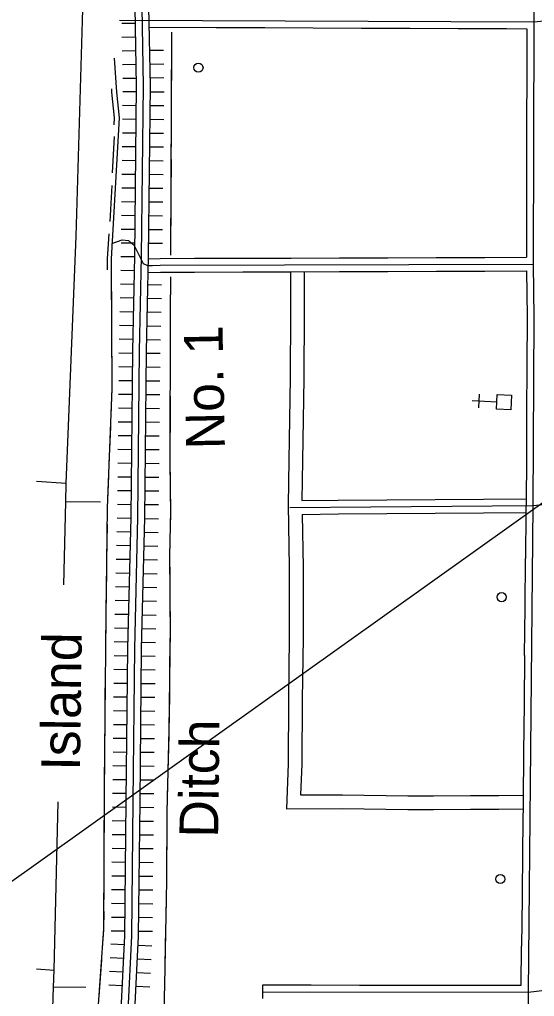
# Model space of a CAD drawing. Extents: x -4306 to 3843, y 131 to 8053.
# Drawn here: x -2826 to -1926, y 1950 to 3654 of the extents above; entities that cross this region are included whole.
import ezdxf

# ---------------------------------------------------------------- set-up
doc = ezdxf.new("R2010")
doc.units = 0
for name, color, linetype in [('29', 7, 'Continuous'), ('31', 7, 'Continuous'), ('32', 7, 'Continuous'), ('4', 7, 'Continuous'), ('43', 7, 'Continuous'), ('45', 7, 'Continuous'), ('46', 7, 'Continuous'), ('5', 7, 'Continuous'), ('56', 7, 'Continuous'), ('57', 7, 'Continuous'), ('R_No Plot', 7, 'Continuous')]:
    doc.layers.add(name, color=color, linetype=linetype)

msp = doc.modelspace()

# ---------------------------------------------------------------- linework, layer by layer
at = {"layer": '29'}
for p, q in [((-2609.1, 3538.2), (-2611.5, 3675.3)), ((-2623, 3647), (-2647, 3646.6)), ((-2622.6, 3623), (-2646.6, 3622.6)), ((-2622.2, 3599.1), (-2646.2, 3598.6)), ((-2622.2, 3599.1), (-2646.2, 3598.6)), ((-2574.2, 3599.9), (-2598.2, 3599.5)), ((-2574.2, 3599.9), (-2598.2, 3599.5)), ((-2621.8, 3575.1), (-2645.8, 3574.6)), ((-2573.8, 3575.9), (-2597.8, 3575.5)), ((-2621.3, 3551.1), (-2645.3, 3550.6)), ((-2573.3, 3551.9), (-2597.3, 3551.5)), ((-2621.2, 3527.4), (-2645.2, 3527.6)), ((-2621.2, 3527.4), (-2645.2, 3527.6)), ((-2612.3, 3240.6), (-2609.1, 3538.2)), ((-2573.2, 3526.9), (-2597.2, 3527.1)), ((-2573.2, 3526.9), (-2597.2, 3527.1)), ((-2621.5, 3503.4), (-2645.5, 3503.6)), ((-2573.5, 3502.9), (-2597.5, 3503.1)), ((-2621.8, 3479.4), (-2645.8, 3479.6)), ((-2573.8, 3478.9), (-2597.8, 3479.1)), ((-2622, 3455.4), (-2646, 3455.6)), ((-2622, 3455.4), (-2646, 3455.6)), ((-2574, 3454.9), (-2598, 3455.1)), ((-2574, 3454.9), (-2598, 3455.1)), ((-2622.3, 3431.4), (-2646.3, 3431.6)), ((-2574.3, 3430.9), (-2598.3, 3431.1)), ((-2622.5, 3407.4), (-2646.5, 3407.6)), ((-2574.5, 3406.9), (-2598.5, 3407.1)), ((-2622.8, 3383.4), (-2646.8, 3383.6)), ((-2622.8, 3383.4), (-2646.8, 3383.6)), ((-2574.8, 3382.9), (-2598.8, 3383.1)), ((-2574.8, 3382.9), (-2598.8, 3383.1)), ((-2623.1, 3359.4), (-2647.1, 3359.6)), ((-2575.1, 3358.9), (-2599.1, 3359.1)), ((-2623.3, 3335.4), (-2647.3, 3335.6)), ((-2575.3, 3334.9), (-2599.3, 3335.1)), ((-2623.6, 3311.4), (-2647.6, 3311.6)), ((-2623.6, 3311.4), (-2647.6, 3311.6)), ((-2575.6, 3310.9), (-2599.6, 3311.1)), ((-2575.6, 3310.9), (-2599.6, 3311.1)), ((-2623.8, 3287.4), (-2647.8, 3287.6)), ((-2575.8, 3286.9), (-2599.8, 3287.1)), ((-2624.1, 3263.4), (-2648.1, 3263.6)), ((-2576.1, 3262.9), (-2600.1, 3263.1)), ((-2624.4, 3239.5), (-2648.4, 3240)), ((-2624.4, 3239.5), (-2648.4, 3240)), ((-2615.9, 3075.5), (-2612.3, 3240.6)), ((-2624.9, 3215.5), (-2648.9, 3216)), ((-2625.4, 3191.5), (-2649.4, 3192)), ((-2577.4, 3190.5), (-2601.4, 3191)), ((-2625.9, 3167.5), (-2649.9, 3168)), ((-2625.9, 3167.5), (-2649.9, 3168)), ((-2577.9, 3166.5), (-2601.9, 3167)), ((-2577.9, 3166.5), (-2601.9, 3167)), ((-2626.4, 3143.5), (-2650.4, 3144)), ((-2578.4, 3142.5), (-2602.4, 3143)), ((-2627, 3119.5), (-2651, 3120)), ((-2579, 3118.5), (-2603, 3119)), ((-2627.5, 3095.5), (-2651.5, 3096)), ((-2627.5, 3095.5), (-2651.5, 3096)), ((-2579.5, 3094.5), (-2603.5, 3095)), ((-2579.5, 3094.5), (-2603.5, 3095)), ((-2627.9, 3071.4), (-2651.9, 3071.6)), ((-2618.8, 2784.8), (-2615.9, 3075.5)), ((-2579.9, 3070.9), (-2603.9, 3071.1)), ((-2628.2, 3047.4), (-2652.2, 3047.6)), ((-2580.2, 3046.9), (-2604.2, 3047.1)), ((-2628.4, 3023.4), (-2652.4, 3023.6)), ((-2628.4, 3023.4), (-2652.4, 3023.6)), ((-2580.4, 3022.9), (-2604.4, 3023.1)), ((-2580.4, 3022.9), (-2604.4, 3023.1)), ((-2628.7, 2999.4), (-2652.7, 2999.6)), ((-2580.7, 2998.9), (-2604.7, 2999.1)), ((-2628.9, 2975.4), (-2652.9, 2975.6)), ((-2580.9, 2974.9), (-2604.9, 2975.1)), ((-2629.1, 2951.4), (-2653.1, 2951.6)), ((-2629.1, 2951.4), (-2653.1, 2951.6)), ((-2581.1, 2950.9), (-2605.1, 2951.1)), ((-2581.1, 2950.9), (-2605.1, 2951.1)), ((-2629.4, 2927.4), (-2653.4, 2927.6)), ((-2581.4, 2926.9), (-2605.4, 2927.1)), ((-2629.6, 2903.4), (-2653.6, 2903.6)), ((-2581.6, 2902.9), (-2605.6, 2903.1)), ((-2629.9, 2879.4), (-2653.9, 2879.6)), ((-2629.9, 2879.4), (-2653.9, 2879.6)), ((-2581.8, 2878.9), (-2605.9, 2879.1)), ((-2581.8, 2878.9), (-2605.9, 2879.1)), ((-2630.1, 2855.4), (-2654.1, 2855.6)), ((-2582.1, 2854.9), (-2606.1, 2855.1)), ((-2630.3, 2831.4), (-2654.3, 2831.6)), ((-2582.3, 2830.9), (-2606.3, 2831.1)), ((-2630.6, 2807.4), (-2654.6, 2807.6)), ((-2630.6, 2807.4), (-2654.6, 2807.6)), ((-2582.6, 2806.9), (-2606.6, 2807.1)), ((-2582.6, 2806.9), (-2606.6, 2807.1)), ((-2630.8, 2783.5), (-2654.8, 2784.1)), ((-2624.3, 2556.4), (-2618.8, 2784.8)), ((-2582.8, 2782.4), (-2606.8, 2783)), ((-2631.4, 2759.5), (-2655.4, 2760.1)), ((-2583.4, 2758.4), (-2607.4, 2759)), ((-2632, 2735.5), (-2656, 2736.1)), ((-2632, 2735.5), (-2656, 2736.1)), ((-2584, 2734.4), (-2608, 2735)), ((-2584, 2734.4), (-2608, 2735)), ((-2632.6, 2711.6), (-2656.6, 2712.1)), ((-2584.6, 2710.4), (-2608.6, 2711)), ((-2633.1, 2687.6), (-2657.1, 2688.1)), ((-2585.2, 2686.4), (-2609.1, 2687)), ((-2633.7, 2663.6), (-2657.7, 2664.1)), ((-2633.7, 2663.6), (-2657.7, 2664.1)), ((-2585.7, 2662.4), (-2609.7, 2663)), ((-2585.7, 2662.4), (-2609.7, 2663)), ((-2634.3, 2639.6), (-2658.3, 2640.1)), ((-2586.3, 2638.4), (-2610.3, 2639)), ((-2634.9, 2615.6), (-2658.9, 2616.1)), ((-2586.9, 2614.4), (-2610.9, 2615)), ((-2635.5, 2591.6), (-2659.5, 2592.2)), ((-2635.5, 2591.6), (-2659.5, 2592.2)), ((-2587.5, 2590.4), (-2611.5, 2591)), ((-2587.5, 2590.4), (-2611.5, 2591)), ((-2636, 2567.6), (-2660, 2568.2)), ((-2627.1, 2290.5), (-2624.3, 2556.4)), ((-2588, 2566.4), (-2612, 2567)), ((-2636.4, 2543.4), (-2660.4, 2543.7)), ((-2588.4, 2542.9), (-2612.4, 2543.2)), ((-2636.7, 2519.4), (-2660.7, 2519.7)), ((-2636.7, 2519.4), (-2660.7, 2519.7)), ((-2588.7, 2518.9), (-2612.7, 2519.2)), ((-2588.7, 2518.9), (-2612.7, 2519.2)), ((-2636.9, 2495.4), (-2661, 2495.7)), ((-2588.9, 2494.9), (-2612.9, 2495.2)), ((-2637.2, 2471.4), (-2661.2, 2471.7)), ((-2589.2, 2470.9), (-2613.2, 2471.2)), ((-2637.5, 2447.4), (-2661.5, 2447.7)), ((-2637.5, 2447.4), (-2661.5, 2447.7)), ((-2589.5, 2446.9), (-2613.5, 2447.2)), ((-2589.5, 2446.9), (-2613.5, 2447.2)), ((-2637.7, 2423.4), (-2661.7, 2423.7)), ((-2589.7, 2422.9), (-2613.7, 2423.2)), ((-2638, 2399.4), (-2662, 2399.7)), ((-2590, 2398.9), (-2614, 2399.2)), ((-2638.2, 2375.4), (-2662.2, 2375.7)), ((-2638.2, 2375.4), (-2662.2, 2375.7)), ((-2590.2, 2374.9), (-2614.2, 2375.2)), ((-2590.2, 2374.9), (-2614.2, 2375.2)), ((-2638.5, 2351.4), (-2662.5, 2351.7)), ((-2590.5, 2350.9), (-2614.5, 2351.2)), ((-2638.7, 2327.4), (-2662.7, 2327.7)), ((-2590.7, 2326.9), (-2614.7, 2327.2)), ((-2639, 2303.4), (-2663, 2303.7)), ((-2639, 2303.4), (-2663, 2303.7)), ((-2591, 2302.9), (-2615, 2303.2)), ((-2591, 2302.9), (-2615, 2303.2)), ((-2629.6, 2055.2), (-2627.1, 2290.5)), ((-2639.2, 2279.4), (-2663.2, 2279.7)), ((-2591.2, 2278.9), (-2615.2, 2279.2)), ((-2639.5, 2255.4), (-2663.5, 2255.7)), ((-2591.5, 2254.9), (-2615.5, 2255.1)), ((-2639.7, 2231.4), (-2663.7, 2231.6)), ((-2639.7, 2231.4), (-2663.7, 2231.6)), ((-2591.7, 2230.9), (-2615.7, 2231.1)), ((-2591.7, 2230.9), (-2615.7, 2231.1)), ((-2640, 2207.4), (-2664, 2207.6)), ((-2592, 2206.9), (-2616, 2207.1)), ((-2640.2, 2183.4), (-2664.2, 2183.6)), ((-2592.2, 2182.9), (-2616.2, 2183.1)), ((-2640.5, 2159.4), (-2664.5, 2159.6)), ((-2640.5, 2159.4), (-2664.5, 2159.6)), ((-2592.5, 2158.9), (-2616.5, 2159.1)), ((-2592.5, 2158.9), (-2616.5, 2159.1)), ((-2640.7, 2135.4), (-2664.7, 2135.6)), ((-2592.7, 2134.9), (-2616.7, 2135.1)), ((-2641, 2111.4), (-2665, 2111.6)), ((-2593, 2110.9), (-2617, 2111.1)), ((-2641.2, 2087.4), (-2665.2, 2087.6)), ((-2641.2, 2087.4), (-2665.2, 2087.6)), ((-2593.2, 2086.9), (-2617.2, 2087.1)), ((-2593.2, 2086.9), (-2617.2, 2087.1)), ((-2641.5, 2063.4), (-2665.5, 2063.6)), ((-2593.5, 2062.9), (-2617.5, 2063.1)), ((-2635.9, 1925.3), (-2629.6, 2055.2)), ((-2642.3, 2039.9), (-2666.3, 2041)), ((-2594.4, 2037.5), (-2618.4, 2038.7)), ((-2643.5, 2015.9), (-2667.5, 2017.1)), ((-2643.5, 2015.9), (-2667.5, 2017.1)), ((-2595.6, 2013.5), (-2619.5, 2014.7)), ((-2595.6, 2013.5), (-2619.5, 2014.7)), ((-2644.7, 1991.9), (-2668.7, 1993.1)), ((-2596.7, 1989.6), (-2620.7, 1990.7)), ((-2645.9, 1967.9), (-2669.8, 1969.1)), ((-2597.9, 1965.6), (-2621.9, 1966.8))]:
    msp.add_line(p, q, dxfattribs=at)
at = {"layer": '31'}
for p, q in [((-1939.9, 3558), (-1940, 3473.5)), ((-1940, 3473.5), (-1940.1, 3389)), ((-1940.1, 3389), (-1940.3, 3239.1)), ((-1940.2, 3215.1), (-1939.2, 3135.4)), ((-1939.2, 3133.3), (-1939.6, 3051.1)), ((-1939.2, 3135.4), (-1939.2, 3133.3)), ((-1940.5, 2882.2), (-1940.9, 2817.8)), ((-1940.9, 2817.8), (-1941.1, 2793.8)), ((-1941.1, 2793.8), (-1941.9, 2713.3)), ((-1943.6, 2544.3), (-1944.4, 2459.8)), ((-1944.4, 2459.8), (-1945.3, 2375.3)), ((-1947, 2206.3), (-1947.9, 2121.9)), ((-1947.9, 2121.9), (-1948.7, 2037.4))]:
    msp.add_line(p, q, dxfattribs=at)
for points in [[(-1939.8, 3637.7), (-1939.9, 3558)], [(-1939.6, 3051.1), (-1940.1, 2966.7)], [(-1940.1, 2966.7), (-1940.5, 2882.2)], [(-1942.7, 2628.8), (-1941.9, 2713.3)], [(-1943.6, 2544.3), (-1942.7, 2628.8)], [(-1945.3, 2375.3), (-1946.2, 2290.8)], [(-1946.2, 2290.8), (-1947, 2206.3)], [(-1949.4, 1969.3), (-1948.7, 2037.4)]]:
    msp.add_lwpolyline(points, dxfattribs=at)
at = {"layer": '32'}
for p, q in [((-2650.8, 3652.7), (-1927.7, 3649.7)), ((-1927.7, 3649.7), (-1898.5, 3652.6)), ((-2598.9, 3640.4), (-2481.9, 3640)), ((-2481.9, 3640), (-2397.4, 3639.6)), ((-2397.4, 3639.6), (-2312.9, 3639.3)), ((-2312.9, 3639.3), (-2228.4, 3638.9)), ((-2228.4, 3638.9), (-2143.9, 3638.6)), ((-2143.9, 3638.6), (-2059.4, 3638.2)), ((-2059.4, 3638.2), (-1974.9, 3637.9)), ((-1974.9, 3637.9), (-1939.8, 3637.7)), ((-2664.5, 3263.3), (-2646.2, 3269.5)), ((-2646.2, 3269.5), (-2635, 3268.1)), ((-2635, 3268.1), (-2625.2, 3259.6)), ((-2625.2, 3259.6), (-2609.9, 3228.3)), ((-2435.7, 3237.5), (-2351.2, 3237.7)), ((-2351.2, 3237.7), (-2266.7, 3238)), ((-2266.7, 3238), (-2182.2, 3238.3)), ((-2182.2, 3238.3), (-2097.7, 3238.6)), ((-2097.7, 3238.6), (-2013.2, 3238.8)), ((-2013.2, 3238.8), (-1940.3, 3239.1)), ((-2609.9, 3228.3), (-2601.9, 3224.6)), ((-2601.9, 3224.6), (-2593.6, 3224.5)), ((-2600.4, 3236.3), (-2580.1, 3237)), ((-2593.6, 3224.5), (-2579.8, 3225)), ((-2580.1, 3237), (-2520.2, 3237.2)), ((-2579.8, 3225), (-1928.3, 3227.1)), ((-2520.2, 3237.2), (-2435.7, 3237.5)), ((-2601, 3212.3), (-2579.6, 3213)), ((-2579.6, 3213), (-2520.1, 3213.2)), ((-2520.1, 3213.2), (-2435.6, 3213.5)), ((-2435.6, 3213.5), (-2351.1, 3213.7)), ((-2351.1, 3213.7), (-2266.6, 3214)), ((-2266.6, 3214), (-2182.1, 3214.3)), ((-2182.1, 3214.3), (-2097.6, 3214.6)), ((-2097.6, 3214.6), (-2013.1, 3214.8)), ((-2013.1, 3214.8), (-1940.2, 3215.1)), ((-2353.3, 2802.5), (-1928.9, 2805.9)), ((-1928.9, 2805.9), (-1902.7, 2808.2)), ((-2400.7, 1945.8), (-2400.7, 1969.8)), ((-2400.7, 1969.8), (-2316.2, 1969.7)), ((-2316.2, 1969.7), (-2231.7, 1969.6)), ((-2231.7, 1969.6), (-2147.2, 1969.5)), ((-2147.2, 1969.5), (-2062.7, 1969.4)), ((-2062.7, 1969.4), (-1978.2, 1969.3)), ((-1978.2, 1969.3), (-1949.4, 1969.3))]:
    msp.add_line(p, q, dxfattribs=at)
for points in [[(-1983.5, 5826.9), (-1984.2, 5591.9), (-1978, 5580.6), (-1963.1, 5563), (-1953.4, 5550.1), (-1949.6, 5541.7), (-1948.4, 5534.6), (-1931.5, 5392.4), (-1927.1, 4704.6), (-1924.6, 4492.3), (-1929.1, 4070.4), (-1927.7, 3649.7), (-1928.3, 3227.1), (-1927.2, 3133.3)], [(-1927.2, 3133.3), (-1928.9, 2805.9), (-1937.5, 1957.3), (-1941.9, 1537.3), (-1945.9, 1118.2), (-1949.1, 657.8)], [(-2400.7, 1957.8), (-1937.5, 1957.3), (-1903.3, 1961)]]:
    msp.add_lwpolyline(points, dxfattribs=at)
at = {"layer": '4'}
for p, q in [((-2715.6, 3651.5), (-2714.2, 3698.1)), ((-2726.5, 3275.8), (-2715.6, 3651.5)), ((-2744, 2844.4), (-2726.5, 3275.8)), ((-2744.8, 2812.3), (-2744, 2844.4)), ((-2748.4, 2667.5), (-2744.8, 2812.3)), ((-2765.3, 1995.4), (-2757.9, 2289.1)), ((-2766, 1965.6), (-2765.3, 1995.4)), ((-2777.4, 1601.5), (-2766, 1965.6))]:
    msp.add_line(p, q, dxfattribs=at)
at = {"layer": '43'}
for points in [[(-2560, 3631.6), (-2561.8, 3242.7)], [(-2560, 3631.6), (-2560.1, 3599.9)], [(-2660, 3586), (-2656.1, 3526.9), (-2651.5, 3482.5), (-2665.7, 3236.5), (-2664.4, 3010), (-2672.3, 2802.1), (-2674.8, 2612), (-2677.7, 2321.3), (-2678.8, 2067.8), (-2689.4, 1918.9), (-2710.5, 1764.8), (-2721.4, 1657.8), (-2742.6, 1525.3)], [(-2560.2, 3578.8), (-2560.5, 3515.4)], [(-2665.1, 3533), (-2664.7, 3526.7), (-2660.1, 3482.3), (-2660.8, 3469.9)], [(-2560.6, 3494.3), (-2560.9, 3430.9)], [(-2660, 3449.4), (-2663.7, 3386.2)], [(-2561, 3409.8), (-2561.3, 3346.5)], [(-2664.3, 3364.4), (-2668, 3301.1)], [(-2561.4, 3325.3), (-2561.7, 3262)], [(-2669.8, 3280.1), (-2672.4, 3236.1), (-2672.3, 3216.8)], [(-2562, 3205), (-2562.3, 3143.3), (-2562.3, 3134.2)], [(-2562, 3205), (-2562.1, 3173.3)], [(-2665.5, 3196), (-2665.1, 3132.6)], [(-2562.2, 3152.2), (-2562.3, 3143.3), (-2562.3, 3134.2)], [(-2562.3, 3134.2), (-2562.8, 2880.1), (-2562.1, 2796.8), (-2563.5, 2718.1), (-2562.6, 2589.4), (-2564.7, 2414.6), (-2568.1, 2271.2), (-2568.8, 2150.6), (-2572.3, 1970.7), (-2573.4, 1924.5), (-2574.5, 1844.9), (-2574, 1763.3), (-2574.4, 1689.7), (-2575.9, 1554)], [(-2562.3, 3134.2), (-2562.4, 3102.5)], [(-2665, 3111.5), (-2664.8, 3079.8)], [(-2664.8, 3079.8), (-2664.6, 3048.1)], [(-2562.4, 3081.4), (-2562.5, 3018.1)], [(-2664.5, 3027), (-2664.4, 3010), (-2666.1, 2963.7)], [(-2562.6, 2996.9), (-2562.7, 2933.6)], [(-2666.9, 2942.6), (-2669.3, 2879.2)], [(-2562.8, 2912.4), (-2562.8, 2880.1), (-2562.6, 2849.1)], [(-2670.1, 2858.1), (-2672.3, 2802.1), (-2672.4, 2794.8)], [(-2562.4, 2828), (-2562.1, 2796.8), (-2562.7, 2764.6)], [(-2672.6, 2773.7), (-2673.5, 2710.3)], [(-2563.1, 2743.5), (-2563.5, 2718.1), (-2563.2, 2680.1)], [(-2673.8, 2689.2), (-2674.6, 2625.8)], [(-2563.1, 2659), (-2562.9, 2627.3)], [(-2562.9, 2627.3), (-2562.6, 2595.6)], [(-2674.9, 2604.7), (-2675.2, 2573)], [(-2562.8, 2574.5), (-2563.5, 2511.1)], [(-2675.2, 2573), (-2675.5, 2541.4)], [(-2675.7, 2520.2), (-2676.3, 2456.9)], [(-2563.8, 2490), (-2564.5, 2426.7)], [(-2676.5, 2435.8), (-2677.2, 2372.4)], [(-2564.9, 2405.5), (-2566.4, 2342.2)], [(-2677.4, 2351.3), (-2677.7, 2321.3), (-2677.8, 2287.9)], [(-2566.9, 2321.1), (-2568.1, 2271.2), (-2568.2, 2257.7)], [(-2677.9, 2266.8), (-2678.2, 2203.4)], [(-2568.3, 2236.6), (-2568.6, 2173.2)], [(-2678.3, 2182.3), (-2678.5, 2118.9)], [(-2568.7, 2152.1), (-2568.8, 2150.6), (-2569.4, 2120.4)], [(-2569.4, 2120.4), (-2570, 2088.8)], [(-2678.6, 2097.8), (-2678.8, 2067.8), (-2678.9, 2066.1)], [(-2678.9, 2066.1), (-2681.1, 2034.5)], [(-2570.4, 2067.6), (-2571.7, 2004.3)], [(-2682.6, 2013.5), (-2687.2, 1950.3)], [(-2572.1, 1983.2), (-2572.3, 1970.7), (-2573.4, 1924.5), (-2573.4, 1919.8)]]:
    msp.add_lwpolyline(points, dxfattribs=at)
at = {"layer": '45'}
for p, q in [((-2268.9, 2815.2), (-2184.4, 2815.9)), ((-2184.4, 2815.9), (-2099.9, 2816.5)), ((-2099.9, 2816.5), (-2015.4, 2817.2)), ((-2015.4, 2817.2), (-1940.9, 2817.8)), ((-2268.7, 2791.2), (-2184.2, 2791.9)), ((-2184.2, 2791.9), (-2099.7, 2792.5)), ((-2099.7, 2792.5), (-2015.3, 2793.2)), ((-2015.3, 2793.2), (-1941.1, 2793.8))]:
    msp.add_line(p, q, dxfattribs=at)
at = {"layer": '46'}
for p, q in [((-2621.1, 3538.2), (-2623.5, 3675.2)), ((-2597.1, 3538.2), (-2599.5, 3675.3)), ((-2624.3, 3240.8), (-2621.1, 3538.2)), ((-2600.3, 3240.4), (-2597.1, 3538.2)), ((-2627.9, 3075.7), (-2624.3, 3240.8)), ((-2603.9, 3075.4), (-2600.3, 3240.4)), ((-2352.6, 3213.7), (-2352.4, 3143.4)), ((-2328.6, 3213.8), (-2328.4, 3143.4)), ((-2352.4, 3143.4), (-2353.1, 3027.9)), ((-2328.4, 3143.4), (-2329.1, 3027.7)), ((-2630.8, 2785), (-2627.9, 3075.7)), ((-2606.8, 2784.6), (-2603.9, 3075.4)), ((-2353.1, 3027.9), (-2355.2, 2884.8)), ((-2329.1, 3027.7), (-2331.2, 2884.4)), ((-2355.2, 2884.8), (-2356.5, 2807)), ((-2331.2, 2884.4), (-2332.4, 2814.6)), ((-2332.4, 2814.6), (-2268.9, 2815.2)), ((-2356.5, 2807), (-2354.4, 2698.3)), ((-2636.3, 2556.6), (-2630.8, 2785)), ((-2612.3, 2556.2), (-2606.8, 2784.6)), ((-2332.2, 2790.6), (-2268.7, 2791.2)), ((-2332.2, 2790.6), (-2330.4, 2698.5)), ((-2354.4, 2698.3), (-2354.4, 2575.9)), ((-2330.4, 2698.5), (-2330.4, 2575.7)), ((-2354.4, 2575.9), (-2355.8, 2467.4)), ((-2330.4, 2575.7), (-2331.8, 2467.2)), ((-2639.1, 2290.6), (-2636.3, 2556.6)), ((-2615.1, 2290.4), (-2612.3, 2556.2)), ((-2355.8, 2467.4), (-2356.3, 2355.3)), ((-2331.8, 2467.2), (-2332.3, 2354.8)), ((-2356.3, 2355.3), (-2359.6, 2277.2)), ((-2332.3, 2354.8), (-2334.6, 2301.2)), ((-2334.6, 2301.2), (-2261.8, 2301.4)), ((-2261.8, 2301.4), (-2147.3, 2299.7)), ((-1988.5, 2300.4), (-1946.1, 2300.8)), ((-2641.6, 2055.5), (-2639.1, 2290.6)), ((-2617.6, 2054.8), (-2615.1, 2290.4)), ((-2147.3, 2299.7), (-2102.5, 2299.5)), ((-2102.5, 2299.5), (-2038.1, 2300.3)), ((-2038.1, 2300.3), (-1988.5, 2300.4)), ((-2359.6, 2277.2), (-2262, 2277.4)), ((-2262, 2277.4), (-2147.5, 2275.7)), ((-2147.5, 2275.7), (-2102.4, 2275.5)), ((-2102.4, 2275.5), (-2038, 2276.3)), ((-2038, 2276.3), (-1988.4, 2276.4)), ((-1988.4, 2276.4), (-1946.3, 2276.8)), ((-2647.9, 1926.2), (-2641.6, 2055.5)), ((-2623.9, 1924.4), (-2617.6, 2054.8))]:
    msp.add_line(p, q, dxfattribs=at)
at = {"layer": '5'}
for p, q in [((-2744, 2844.4), (-2796.1, 2847.8)), ((-2684.1, 2812), (-2744.8, 2812.3)), ((-2796.1, 1997.9), (-2765.3, 1995.4)), ((-2709.8, 1965.1), (-2766, 1965.6))]:
    msp.add_line(p, q, dxfattribs=at)
at = {"layer": '56'}
for centre in [(-2513.1, 3569.8), (-1983.7, 2646.2), (-1985.9, 2154.5)]:
    msp.add_circle(centre, 8, dxfattribs=at)
at = {"layer": '57'}
for p, q in [((-2023.7, 2976.5), (-2022.5, 3000.4)), ((-2035.1, 2989), (-1992.1, 2986.9))]:
    msp.add_line(p, q, dxfattribs=at)
msp.add_lwpolyline([(-1967.8, 2972.7), (-1992.7, 2974), (-1991.5, 2999.8), (-1966.5, 2998.6)], close=True, dxfattribs=at)
at = {"layer": 'R_No Plot'}
msp.add_line((-2855, 2139.1), (-750.7, 3638.5), dxfattribs=at)

# ---------------------------------------------------------------- texts
at = {"layer": '43'}
for s, rotation, p in [('No. 1', 91.1621, (-2466.8, 2904.6)), ('Island', 89.1621, (-2720.2, 2343.1)), ('Ditch', 89.333, (-2478.8, 2226.4))]:
    msp.add_text(s, height=67.59, rotation=rotation, dxfattribs=at).set_placement(p)

doc.saveas('drawing.dxf')
